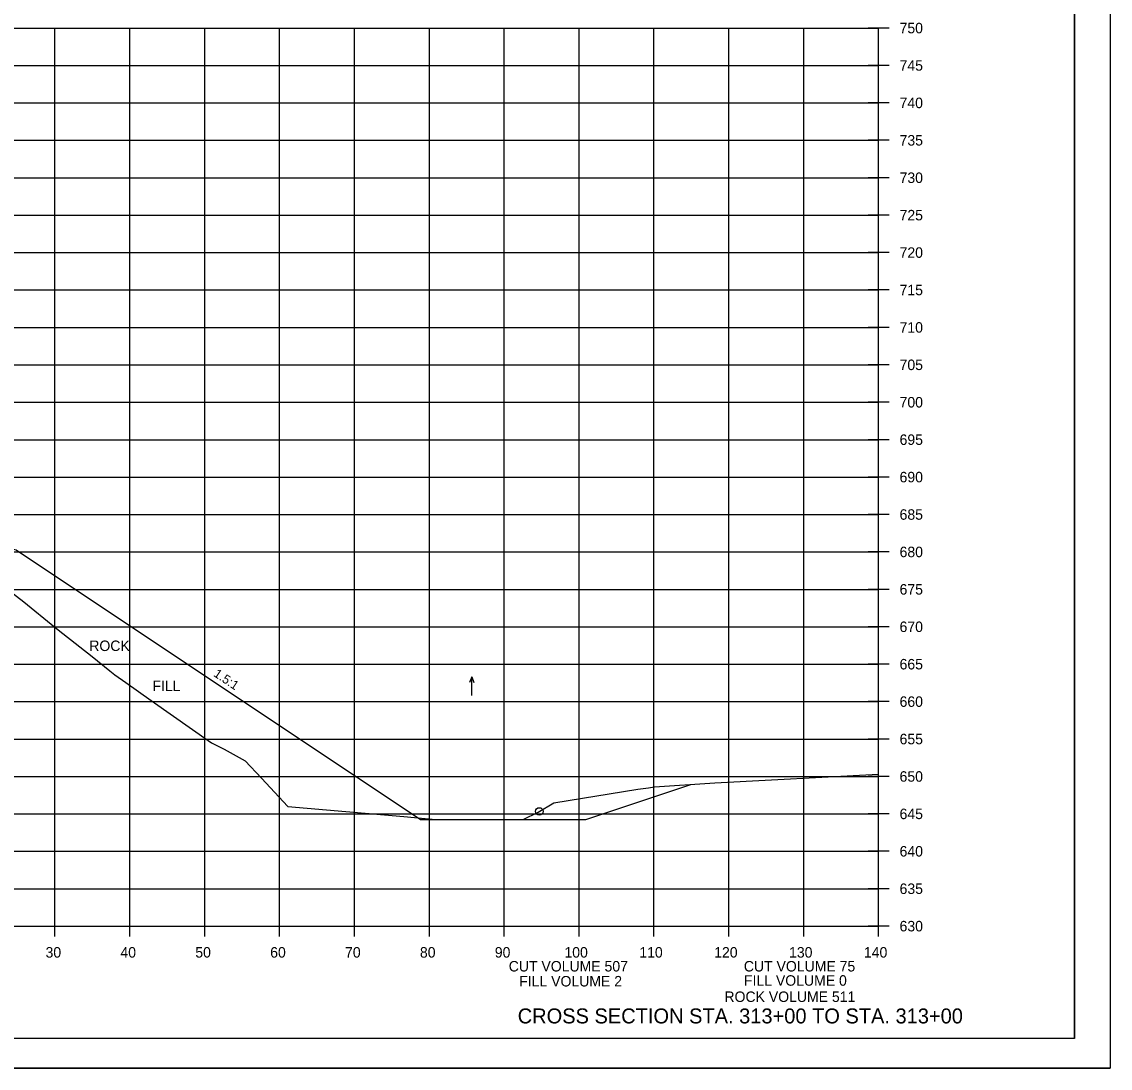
# Model space of a CAD drawing. Extents: x 1370515 to 1370849, y 383299 to 386073.
# Drawn here: x 1370703.4 to 1370848.7, y 385646.1 to 385786 of the extents above; entities that cross this region are included whole.
import ezdxf

# ---------------------------------------------------------------- set-up
doc = ezdxf.new("R2010")
doc.units = 0
for name, color, linetype in [('R_Axis', 7, 'Continuous'), ('R_Axis Annot', 7, 'Continuous'), ('R_Border', 7, 'Continuous'), ('R_Draft', 7, 'Continuous'), ('R_Exist Surface', 7, 'Continuous'), ('R_Fin Surface', 7, 'Continuous'), ('R_Grid', 7, 'Continuous'), ('R_No Plot', 7, 'Continuous'), ('R_Water Annot', 7, 'Continuous')]:
    doc.layers.add(name, color=color, linetype=linetype)

msp = doc.modelspace()

# ---------------------------------------------------------------- linework, layer by layer
at = {"layer": 'R_Axis'}
for p, q in [((1370819.2, 385785.13), (1370816.4, 385785.13)), ((1370817.8, 385665.13), (1370817.8, 385785.13)), ((1370819.2, 385780.13), (1370816.4, 385780.13)), ((1370819.2, 385775.13), (1370816.4, 385775.13)), ((1370819.2, 385770.13), (1370816.4, 385770.13)), ((1370819.2, 385765.13), (1370816.4, 385765.13)), ((1370819.2, 385760.13), (1370816.4, 385760.13)), ((1370819.2, 385755.13), (1370816.4, 385755.13)), ((1370819.2, 385750.13), (1370816.4, 385750.13)), ((1370819.2, 385745.13), (1370816.4, 385745.13)), ((1370819.2, 385740.13), (1370816.4, 385740.13)), ((1370819.2, 385735.13), (1370816.4, 385735.13)), ((1370819.2, 385730.13), (1370816.4, 385730.13)), ((1370819.2, 385725.13), (1370816.4, 385725.13)), ((1370819.2, 385720.13), (1370816.4, 385720.13)), ((1370819.2, 385715.13), (1370816.4, 385715.13)), ((1370819.2, 385710.13), (1370816.4, 385710.13)), ((1370819.2, 385705.13), (1370816.4, 385705.13)), ((1370819.2, 385700.13), (1370816.4, 385700.13)), ((1370819.2, 385695.13), (1370816.4, 385695.13)), ((1370819.2, 385690.13), (1370816.4, 385690.13)), ((1370819.2, 385685.13), (1370816.4, 385685.13)), ((1370819.2, 385680.13), (1370816.4, 385680.13)), ((1370819.2, 385675.13), (1370816.4, 385675.13)), ((1370819.2, 385670.13), (1370816.4, 385670.13)), ((1370707.8, 385663.73), (1370707.8, 385666.53)), ((1370717.8, 385663.73), (1370717.8, 385666.53)), ((1370727.8, 385663.73), (1370727.8, 385666.53)), ((1370737.8, 385663.73), (1370737.8, 385666.53)), ((1370747.8, 385663.73), (1370747.8, 385666.53)), ((1370757.8, 385663.73), (1370757.8, 385666.53)), ((1370767.8, 385663.73), (1370767.8, 385666.53)), ((1370777.8, 385663.73), (1370777.8, 385666.53)), ((1370787.8, 385663.73), (1370787.8, 385666.53)), ((1370797.8, 385663.73), (1370797.8, 385666.53)), ((1370807.8, 385663.73), (1370807.8, 385666.53)), ((1370817.8, 385663.73), (1370817.8, 385666.53)), ((1370537.8, 385665.13), (1370817.8, 385665.13)), ((1370819.2, 385665.13), (1370816.4, 385665.13))]:
    msp.add_line(p, q, dxfattribs=at)
at = {"layer": 'R_Border'}
for q in [(1370843.98, 385855.59), (1370527.8, 385650.13)]:
    msp.add_line((1370843.98, 385650.13), q, dxfattribs=at)
at = {"layer": 'R_Exist Surface'}
msp.add_lwpolyline([(1370700.68, 385710.73), (1370703.66, 385708.46), (1370707.77, 385705.08), (1370708.86, 385704.21), (1370712.76, 385701.14), (1370715.14, 385699.26), (1370715.8, 385698.7), (1370717.24, 385697.68), (1370720.63, 385695.28), (1370728.68, 385689.61), (1370730.4, 385688.77), (1370733.19, 385687.23), (1370735.4, 385684.9), (1370738.91, 385681.11), (1370754.4, 385679.78), (1370758.66, 385679.39), (1370760.94, 385679.39), (1370770.31, 385679.37), (1370772.34, 385680.37), (1370774.41, 385681.6), (1370785.63, 385683.41), (1370787.08, 385683.59), (1370787.89, 385683.73), (1370795.93, 385684.26), (1370817.8, 385685.44)], dxfattribs=at)
at = {"layer": 'R_Fin Surface'}
msp.add_lwpolyline([(1370579.35, 385755.05), (1370635.3, 385727.08), (1370640.3, 385727.08), (1370643.61, 385713.83), (1370653.61, 385713.83), (1370659.43, 385715.28), (1370665.8, 385715.59), (1370689.8, 385716.73), (1370696.6, 385716.9), (1370702.6, 385715.4), (1370756.63, 385679.37), (1370778.7, 385679.37), (1370792.73, 385684.05)], dxfattribs=at)
at = {"layer": 'R_Grid'}
for p, q in [((1370537.8, 385785.13), (1370817.8, 385785.13)), ((1370707.8, 385665.13), (1370707.8, 385785.13)), ((1370717.8, 385665.13), (1370717.8, 385785.13)), ((1370727.8, 385665.13), (1370727.8, 385785.13)), ((1370737.8, 385665.13), (1370737.8, 385785.13)), ((1370747.8, 385665.13), (1370747.8, 385785.13)), ((1370757.8, 385665.13), (1370757.8, 385785.13)), ((1370767.8, 385665.13), (1370767.8, 385785.13)), ((1370777.8, 385665.13), (1370777.8, 385785.13)), ((1370787.8, 385665.13), (1370787.8, 385785.13)), ((1370797.8, 385665.13), (1370797.8, 385785.13)), ((1370807.8, 385665.13), (1370807.8, 385785.13)), ((1370817.8, 385665.13), (1370817.8, 385785.13)), ((1370537.8, 385780.13), (1370817.8, 385780.13)), ((1370537.8, 385775.13), (1370817.8, 385775.13)), ((1370537.8, 385770.13), (1370817.8, 385770.13)), ((1370537.8, 385765.13), (1370817.8, 385765.13)), ((1370537.8, 385760.13), (1370817.8, 385760.13)), ((1370537.8, 385755.13), (1370817.8, 385755.13)), ((1370537.8, 385750.13), (1370817.8, 385750.13)), ((1370537.8, 385745.13), (1370817.8, 385745.13)), ((1370537.8, 385740.13), (1370817.8, 385740.13)), ((1370537.8, 385735.13), (1370817.8, 385735.13)), ((1370537.8, 385730.13), (1370817.8, 385730.13)), ((1370537.8, 385725.13), (1370817.8, 385725.13)), ((1370537.8, 385720.13), (1370817.8, 385720.13)), ((1370537.8, 385715.13), (1370817.8, 385715.13)), ((1370537.8, 385710.13), (1370817.8, 385710.13)), ((1370537.8, 385705.13), (1370817.8, 385705.13)), ((1370537.8, 385700.13), (1370817.8, 385700.13)), ((1370537.8, 385695.13), (1370817.8, 385695.13)), ((1370537.8, 385690.13), (1370817.8, 385690.13)), ((1370537.8, 385685.13), (1370817.8, 385685.13)), ((1370537.8, 385680.13), (1370817.8, 385680.13)), ((1370537.8, 385675.13), (1370817.8, 385675.13)), ((1370537.8, 385670.13), (1370817.8, 385670.13)), ((1370537.8, 385665.13), (1370817.8, 385665.13))]:
    msp.add_line(p, q, dxfattribs=at)
at = {"layer": 'R_No Plot'}
msp.add_line((1370515.4, 385646.15), (1370848.73, 385646.15), dxfattribs=at)
for points in [[(1370515.39, 385859.48), (1370848.73, 385859.48), (1370848.73, 385646.14), (1370515.39, 385646.14)], [(1370761.72, 385855.59), (1370761.72, 385845.71), (1370797.45, 385845.71), (1370797.45, 385842.79), (1370820.65, 385842.79), (1370820.65, 385819.57), (1370843.98, 385819.57), (1370843.98, 385650.13), (1370527.8, 385650.13), (1370527.8, 385855.59)]]:
    msp.add_lwpolyline(points, close=True, dxfattribs=at)
msp.add_circle((1370772.48, 385680.46), 0.5, dxfattribs=at)
at = {"layer": 'R_Water Annot'}
for p, q in [((1370763.46, 385698.44), (1370763.18, 385697.67)), ((1370763.46, 385695.93), (1370763.46, 385698.44)), ((1370763.46, 385698.44), (1370763.74, 385697.67))]:
    msp.add_line(p, q, dxfattribs=at)

# ---------------------------------------------------------------- texts
at = {"layer": 'R_Axis Annot'}
for s, p in [('750', (1370820.6, 385784.43)), ('745', (1370820.6, 385779.43)), ('740', (1370820.6, 385774.43)), ('735', (1370820.6, 385769.43)), ('730', (1370820.6, 385764.43)), ('725', (1370820.6, 385759.43)), ('720', (1370820.6, 385754.43)), ('715', (1370820.6, 385749.43)), ('710', (1370820.6, 385744.43)), ('705', (1370820.6, 385739.43)), ('700', (1370820.6, 385734.43)), ('695', (1370820.6, 385729.43)), ('690', (1370820.6, 385724.43)), ('685', (1370820.6, 385719.43)), ('680', (1370820.6, 385714.43)), ('675', (1370820.6, 385709.43)), ('670', (1370820.6, 385704.43)), ('ROCK', (1370712.38, 385701.89)), ('665', (1370820.6, 385699.43)), ('FILL', (1370720.81, 385696.53)), ('660', (1370820.6, 385694.43)), ('655', (1370820.6, 385689.43)), ('650', (1370820.6, 385684.43)), ('645', (1370820.6, 385679.43)), ('640', (1370820.6, 385674.43)), ('635', (1370820.6, 385669.43)), ('630', (1370820.6, 385664.43)), ('30', (1370706.54, 385660.93)), ('40', (1370716.54, 385660.93)), ('50', (1370726.54, 385660.93)), ('60', (1370736.54, 385660.93)), ('70', (1370746.54, 385660.93)), ('80', (1370756.54, 385660.93)), ('90', (1370766.54, 385660.93)), ('100', (1370775.84, 385660.93)), ('110', (1370785.84, 385660.93)), ('120', (1370795.84, 385660.93)), ('130', (1370805.84, 385660.93)), ('140', (1370815.84, 385660.93)), ('CUT VOLUME 507', (1370768.4, 385659.07)), ('CUT VOLUME 75', (1370799.8, 385659.07)), ('FILL VOLUME 2', (1370769.8, 385657.07)), ('FILL VOLUME 0', (1370799.82, 385657.17)), ('ROCK VOLUME 511', (1370797.21, 385655))]:
    msp.add_text(s, height=1.4, dxfattribs=at).set_placement(p)
at = {"layer": 'R_Draft'}
msp.add_text('CROSS SECTION STA. 313+00 TO STA. 313+00', height=2, dxfattribs=at).set_placement((1370769.6, 385652.13))
at = {"layer": 'R_Fin Surface'}
msp.add_text('1.5:1', height=1.2, rotation=326.3099, dxfattribs=at).set_placement((1370728.88, 385698.6))
at = {"layer": 'R_No Plot'}
for p in [(1370703.62, 385708.41), (1370708.82, 385704.16), (1370715.76, 385698.65), (1370728.64, 385689.56), (1370733.14, 385687.18), (1370787.85, 385683.68), (1370738.86, 385681.06), (1370774.37, 385681.55), (1370758.61, 385679.34), (1370770.27, 385679.32)]:
    msp.add_text('+', height=0.1, dxfattribs=at).set_placement(p)

doc.saveas('drawing.dxf')
